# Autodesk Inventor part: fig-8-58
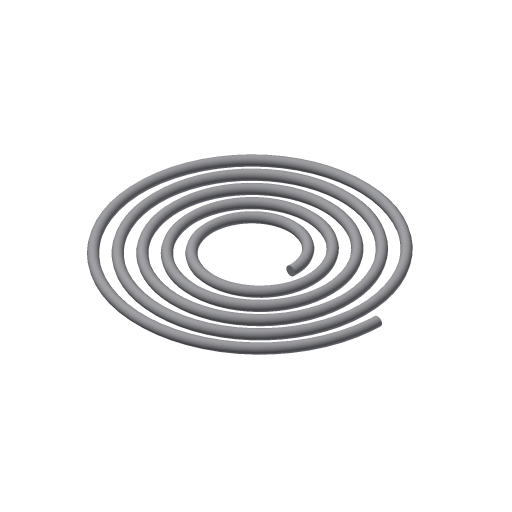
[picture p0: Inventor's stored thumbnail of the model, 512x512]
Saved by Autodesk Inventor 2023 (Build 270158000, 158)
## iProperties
Created: 2002-01
Part Number: fig-8-58
Document SubType Name: Modeling
Designer: CADSoft
Density: 1 g/cm^3
Material: Generic
Appearance: Default
Control State: 0
Master: False
Checked Out: False
Shininess: 77.0
Length Units: 11269
Angle Units: 11279
Time Units: 11290
Mass Units: 11283
Length Display Precision: 3
Angle Display Precision: 2
Density: 0.0
Volumn: 0.0
Area: 0.0
PropertySet Name: Model Information
Author: CADSoft
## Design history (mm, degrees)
sketch "Sketch2"
  geometry: C1 r 2.5 at (-19.895, -0.092)
  constraints: 1 centre point
  dimensions: "d0" = 5 diameter of C1
coil "Coil5" sketch "Sketch2" pitch "d35" = 10; turns "d37" = 5; dims "d36" = 10, "d38" = 0, angle "d39" = 90 deg, angle "d40" = 90 deg, "d41" = 0, "d42" = 0
body "Solid1"
